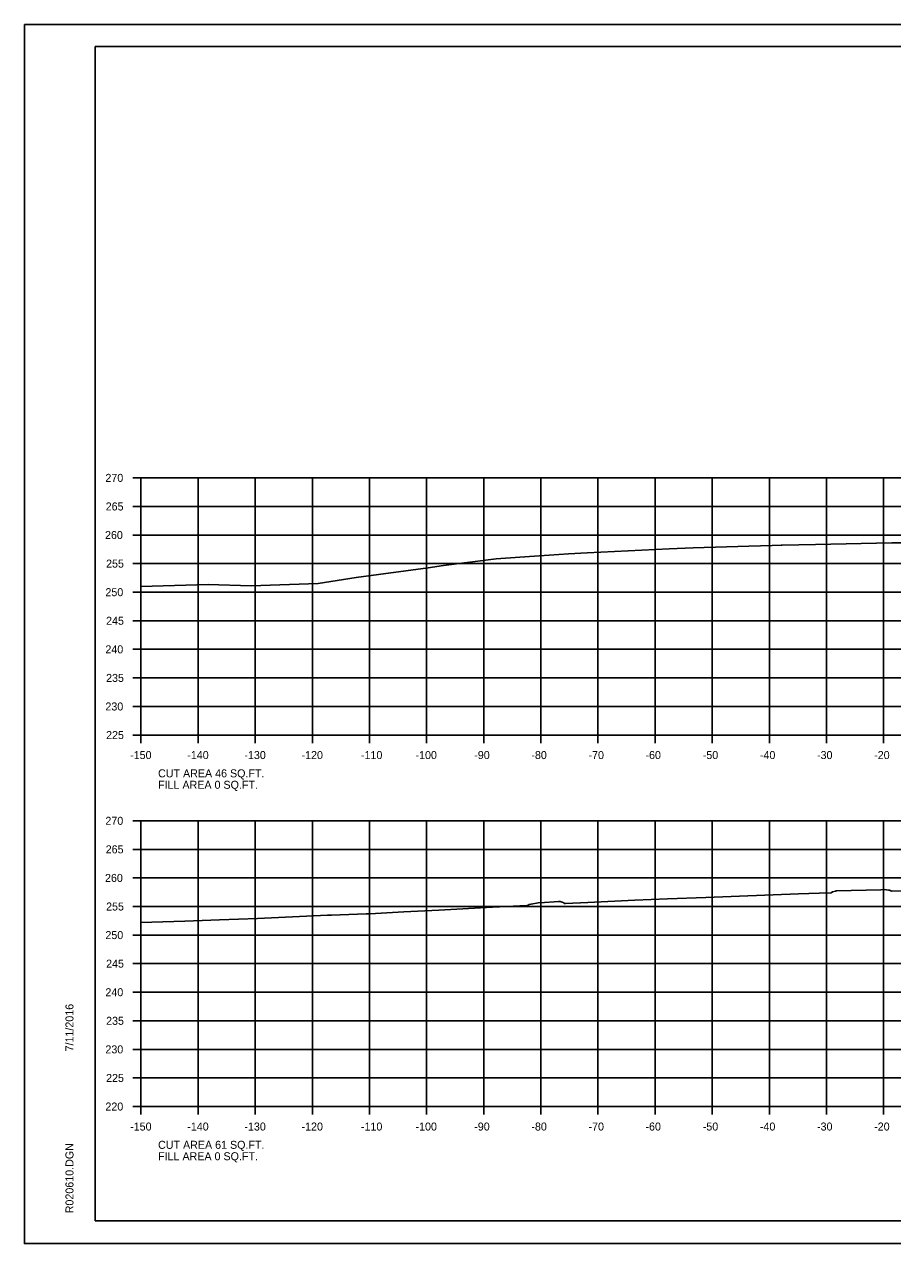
# Model space of a CAD drawing. Extents: x 1103485 to 1107180, y 2010593 to 2011873.
# Drawn here: x 1106846.8 to 1106998.8, y 2011659.5 to 2011872.9 of the extents above; entities that cross this region are included whole.
import ezdxf

# ---------------------------------------------------------------- set-up
doc = ezdxf.new("R2010")
doc.units = 0
for name, color, linetype in [('R_Axis', 7, 'Continuous'), ('R_Axis Annot', 7, 'Continuous'), ('R_Border', 7, 'Continuous'), ('R_Exist Surface', 7, 'Continuous'), ('R_Grid', 7, 'Continuous'), ('R_No Plot', 7, 'Continuous')]:
    doc.layers.add(name, color=color, linetype=linetype)

msp = doc.modelspace()

# ---------------------------------------------------------------- linework, layer by layer
at = {"layer": 'R_Axis'}
for p, q in [((1106865.78, 2011793.51), (1106867.18, 2011793.51)), ((1106867.18, 2011748.51), (1106867.18, 2011793.51)), ((1106865.78, 2011788.51), (1106867.18, 2011788.51)), ((1106865.78, 2011783.51), (1106867.18, 2011783.51)), ((1106865.78, 2011778.51), (1106867.18, 2011778.51)), ((1106865.78, 2011773.51), (1106867.18, 2011773.51)), ((1106865.78, 2011768.51), (1106867.18, 2011768.51)), ((1106865.78, 2011763.51), (1106867.18, 2011763.51)), ((1106865.78, 2011758.51), (1106867.18, 2011758.51)), ((1106865.78, 2011753.51), (1106867.18, 2011753.51)), ((1106865.78, 2011748.51), (1106867.18, 2011748.51)), ((1106867.18, 2011748.51), (1107167.18, 2011748.51)), ((1106867.18, 2011747.11), (1106867.18, 2011748.51)), ((1106877.18, 2011747.11), (1106877.18, 2011748.51)), ((1106887.18, 2011747.11), (1106887.18, 2011748.51)), ((1106897.18, 2011747.11), (1106897.18, 2011748.51)), ((1106907.18, 2011747.11), (1106907.18, 2011748.51)), ((1106917.18, 2011747.11), (1106917.18, 2011748.51)), ((1106927.18, 2011747.11), (1106927.18, 2011748.51)), ((1106937.18, 2011747.11), (1106937.18, 2011748.51)), ((1106947.18, 2011747.11), (1106947.18, 2011748.51)), ((1106957.18, 2011747.11), (1106957.18, 2011748.51)), ((1106967.18, 2011747.11), (1106967.18, 2011748.51)), ((1106977.18, 2011747.11), (1106977.18, 2011748.51)), ((1106987.18, 2011747.11), (1106987.18, 2011748.51)), ((1106997.18, 2011747.11), (1106997.18, 2011748.51)), ((1106865.78, 2011733.51), (1106867.18, 2011733.51)), ((1106867.18, 2011683.51), (1106867.18, 2011733.51)), ((1106865.78, 2011728.51), (1106867.18, 2011728.51)), ((1106865.78, 2011723.51), (1106867.18, 2011723.51)), ((1106865.78, 2011718.51), (1106867.18, 2011718.51)), ((1106865.78, 2011713.51), (1106867.18, 2011713.51)), ((1106865.78, 2011708.51), (1106867.18, 2011708.51)), ((1106865.78, 2011703.51), (1106867.18, 2011703.51)), ((1106865.78, 2011698.51), (1106867.18, 2011698.51)), ((1106865.78, 2011693.51), (1106867.18, 2011693.51)), ((1106865.78, 2011688.51), (1106867.18, 2011688.51)), ((1106865.78, 2011683.51), (1106867.18, 2011683.51)), ((1106867.18, 2011683.51), (1107167.18, 2011683.51)), ((1106867.18, 2011682.11), (1106867.18, 2011683.51)), ((1106877.18, 2011682.11), (1106877.18, 2011683.51)), ((1106887.18, 2011682.11), (1106887.18, 2011683.51)), ((1106897.18, 2011682.11), (1106897.18, 2011683.51)), ((1106907.18, 2011682.11), (1106907.18, 2011683.51)), ((1106917.18, 2011682.11), (1106917.18, 2011683.51)), ((1106927.18, 2011682.11), (1106927.18, 2011683.51)), ((1106937.18, 2011682.11), (1106937.18, 2011683.51)), ((1106947.18, 2011682.11), (1106947.18, 2011683.51)), ((1106957.18, 2011682.11), (1106957.18, 2011683.51)), ((1106967.18, 2011682.11), (1106967.18, 2011683.51)), ((1106977.18, 2011682.11), (1106977.18, 2011683.51)), ((1106987.18, 2011682.11), (1106987.18, 2011683.51)), ((1106997.18, 2011682.11), (1106997.18, 2011683.51))]:
    msp.add_line(p, q, dxfattribs=at)
at = {"layer": 'R_Border'}
for p, q in [((1106859.18, 2011868.97), (1107175.36, 2011868.97)), ((1106859.18, 2011663.51), (1106859.18, 2011868.97)), ((1106859.18, 2011663.51), (1106859.18, 2011663.51)), ((1107175.36, 2011663.51), (1106859.18, 2011663.51))]:
    msp.add_line(p, q, dxfattribs=at)
at = {"layer": 'R_Exist Surface'}
for points in [[(1106867.18, 2011774.5), (1106878.95, 2011774.88), (1106886.46, 2011774.64), (1106898.2, 2011775.03), (1106904.85, 2011776.09), (1106917.48, 2011777.78), (1106920.12, 2011778.18), (1106929.33, 2011779.36), (1106933.47, 2011779.64), (1106938.61, 2011779.97), (1106941.99, 2011780.22), (1106945.26, 2011780.41), (1106959.62, 2011781.09), (1106963.82, 2011781.26), (1106973.61, 2011781.55), (1106977.69, 2011781.66), (1106979.24, 2011781.71), (1106979.43, 2011781.71), (1106985.23, 2011781.84), (1106998.64, 2011782.16), (1107001.63, 2011782.17)], [(1106867.18, 2011715.69), (1106874.84, 2011715.95), (1106880.92, 2011716.18), (1106887.61, 2011716.44), (1106899.81, 2011716.98), (1106900.52, 2011717), (1106906.58, 2011717.23), (1106907.27, 2011717.25), (1106913.2, 2011717.56), (1106919.35, 2011717.87), (1106928.72, 2011718.38), (1106934.75, 2011718.7), (1106934.9, 2011718.71), (1106934.97, 2011718.75), (1106935.15, 2011718.87), (1106935.48, 2011718.93), (1106936.7, 2011719.15), (1106937.82, 2011719.21), (1106939.5, 2011719.32), (1106940.29, 2011719.38), (1106940.58, 2011719.38), (1106940.89, 2011719.28), (1106941.18, 2011719.18), (1106941.24, 2011719.09), (1106941.28, 2011719.03), (1106941.47, 2011719.05), (1106945.41, 2011719.22), (1106953.65, 2011719.64), (1106959.33, 2011719.84), (1106966.03, 2011720.08), (1106982.27, 2011720.71), (1106985.88, 2011720.85), (1106987.97, 2011720.91), (1106988.21, 2011721.08), (1106988.23, 2011721.1), (1106988.74, 2011721.22), (1106988.91, 2011721.24), (1106996.66, 2011721.45), (1106997.34, 2011721.46), (1106998.05, 2011721.37), (1106998.22, 2011721.36), (1106998.43, 2011721.27), (1106998.58, 2011721.22), (1107013.75, 2011721.54)]]:
    msp.add_lwpolyline(points, dxfattribs=at)
at = {"layer": 'R_Grid'}
for p, q in [((1106867.18, 2011793.51), (1107167.18, 2011793.51)), ((1106867.18, 2011748.51), (1106867.18, 2011793.51)), ((1106877.18, 2011748.51), (1106877.18, 2011793.51)), ((1106887.18, 2011748.51), (1106887.18, 2011793.51)), ((1106897.18, 2011748.51), (1106897.18, 2011793.51)), ((1106907.18, 2011748.51), (1106907.18, 2011793.51)), ((1106917.18, 2011748.51), (1106917.18, 2011793.51)), ((1106927.18, 2011748.51), (1106927.18, 2011793.51)), ((1106937.18, 2011748.51), (1106937.18, 2011793.51)), ((1106947.18, 2011748.51), (1106947.18, 2011793.51)), ((1106957.18, 2011748.51), (1106957.18, 2011793.51)), ((1106967.18, 2011748.51), (1106967.18, 2011793.51)), ((1106977.18, 2011748.51), (1106977.18, 2011793.51)), ((1106987.18, 2011748.51), (1106987.18, 2011793.51)), ((1106997.18, 2011748.51), (1106997.18, 2011793.51)), ((1106867.18, 2011788.51), (1107167.18, 2011788.51)), ((1106867.18, 2011783.51), (1107167.18, 2011783.51)), ((1106867.18, 2011778.51), (1107167.18, 2011778.51)), ((1106867.18, 2011773.51), (1107167.18, 2011773.51)), ((1106867.18, 2011768.51), (1107167.18, 2011768.51)), ((1106867.18, 2011763.51), (1107167.18, 2011763.51)), ((1106867.18, 2011758.51), (1107167.18, 2011758.51)), ((1106867.18, 2011753.51), (1107167.18, 2011753.51)), ((1106867.18, 2011748.51), (1107167.18, 2011748.51)), ((1106867.18, 2011733.51), (1107167.18, 2011733.51)), ((1106867.18, 2011683.51), (1106867.18, 2011733.51)), ((1106877.18, 2011683.51), (1106877.18, 2011733.51)), ((1106887.18, 2011683.51), (1106887.18, 2011733.51)), ((1106897.18, 2011683.51), (1106897.18, 2011733.51)), ((1106907.18, 2011683.51), (1106907.18, 2011733.51)), ((1106917.18, 2011683.51), (1106917.18, 2011733.51)), ((1106927.18, 2011683.51), (1106927.18, 2011733.51)), ((1106937.18, 2011683.51), (1106937.18, 2011733.51)), ((1106947.18, 2011683.51), (1106947.18, 2011733.51)), ((1106957.18, 2011683.51), (1106957.18, 2011733.51)), ((1106967.18, 2011683.51), (1106967.18, 2011733.51)), ((1106977.18, 2011683.51), (1106977.18, 2011733.51)), ((1106987.18, 2011683.51), (1106987.18, 2011733.51)), ((1106997.18, 2011683.51), (1106997.18, 2011733.51)), ((1106867.18, 2011728.51), (1107167.18, 2011728.51)), ((1106867.18, 2011723.51), (1107167.18, 2011723.51)), ((1106867.18, 2011718.51), (1107167.18, 2011718.51)), ((1106867.18, 2011713.51), (1107167.18, 2011713.51)), ((1106867.18, 2011708.51), (1107167.18, 2011708.51)), ((1106867.18, 2011703.51), (1107167.18, 2011703.51)), ((1106867.18, 2011698.51), (1107167.18, 2011698.51)), ((1106867.18, 2011693.51), (1107167.18, 2011693.51)), ((1106867.18, 2011688.51), (1107167.18, 2011688.51)), ((1106867.18, 2011683.51), (1107167.18, 2011683.51))]:
    msp.add_line(p, q, dxfattribs=at)
at = {"layer": 'R_No Plot'}
for p, q in [((1106846.78, 2011872.86), (1107180.12, 2011872.86)), ((1106846.78, 2011659.53), (1107180.12, 2011659.53))]:
    msp.add_line(p, q, dxfattribs=at)
for points in [[(1106846.78, 2011872.86), (1107180.12, 2011872.86), (1107180.12, 2011659.52), (1106846.78, 2011659.52)], [(1107093.1, 2011868.97), (1107093.1, 2011859.09), (1107128.84, 2011859.09), (1107128.84, 2011856.17), (1107152.04, 2011856.17), (1107152.04, 2011831.83), (1107175.36, 2011831.83), (1107175.36, 2011663.51), (1106859.18, 2011663.51), (1106859.18, 2011868.97)]]:
    msp.add_lwpolyline(points, close=True, dxfattribs=at)

# ---------------------------------------------------------------- texts
at = {"layer": 'R_Axis Annot'}
for s, p in [('270', (1106860.96, 2011792.81)), ('265', (1106861.01, 2011787.81)), ('260', (1106860.89, 2011782.81)), ('255', (1106861.08, 2011777.81)), ('250', (1106860.96, 2011772.81)), ('245', (1106861.08, 2011767.81)), ('240', (1106860.96, 2011762.81)), ('235', (1106861.08, 2011757.81)), ('230', (1106860.96, 2011752.81)), ('225', (1106861.08, 2011747.81)), ('-150', (1106865.29, 2011744.31)), ('-140', (1106875.29, 2011744.31)), ('-130', (1106885.29, 2011744.31)), ('-120', (1106895.29, 2011744.31)), ('-110', (1106905.69, 2011744.31)), ('-100', (1106915.24, 2011744.31)), ('-90', (1106925.52, 2011744.31)), ('-80', (1106935.52, 2011744.31)), ('-70', (1106945.52, 2011744.31)), ('-60', (1106955.49, 2011744.31)), ('-50', (1106965.52, 2011744.31)), ('-40', (1106975.52, 2011744.31)), ('-30', (1106985.52, 2011744.31)), ('-20', (1106995.52, 2011744.31)), ('CUT AREA 46 SQ.FT.', (1106870.18, 2011741.11)), ('FILL AREA 0 SQ.FT.', (1106870.18, 2011739.11)), ('270', (1106860.96, 2011732.81)), ('265', (1106861.01, 2011727.81)), ('260', (1106860.89, 2011722.81)), ('255', (1106861.08, 2011717.81)), ('250', (1106860.96, 2011712.81)), ('245', (1106861.08, 2011707.81)), ('240', (1106860.96, 2011702.81)), ('235', (1106861.08, 2011697.81)), ('230', (1106860.96, 2011692.81)), ('225', (1106861.08, 2011687.81)), ('220', (1106860.96, 2011682.81)), ('-150', (1106865.29, 2011679.31)), ('-140', (1106875.29, 2011679.31)), ('-130', (1106885.29, 2011679.31)), ('-120', (1106895.29, 2011679.31)), ('-110', (1106905.69, 2011679.31)), ('-100', (1106915.24, 2011679.31)), ('-90', (1106925.52, 2011679.31)), ('-80', (1106935.52, 2011679.31)), ('-70', (1106945.52, 2011679.31)), ('-60', (1106955.49, 2011679.31)), ('-50', (1106965.52, 2011679.31)), ('-40', (1106975.52, 2011679.31)), ('-30', (1106985.52, 2011679.31)), ('-20', (1106995.52, 2011679.31)), ('CUT AREA 61 SQ.FT.', (1106870.18, 2011676.11)), ('FILL AREA 0 SQ.FT.', (1106870.18, 2011674.11))]:
    msp.add_text(s, height=1.4, dxfattribs=at).set_placement(p)
at = {"layer": 'R_Border'}
for s, p in [('7/11/2016', (1106855.37, 2011693.15)), ('R020610.DGN', (1106855.37, 2011664.83))]:
    msp.add_text(s, height=1.4, rotation=90, dxfattribs=at).set_placement(p)

doc.saveas('drawing.dxf')
